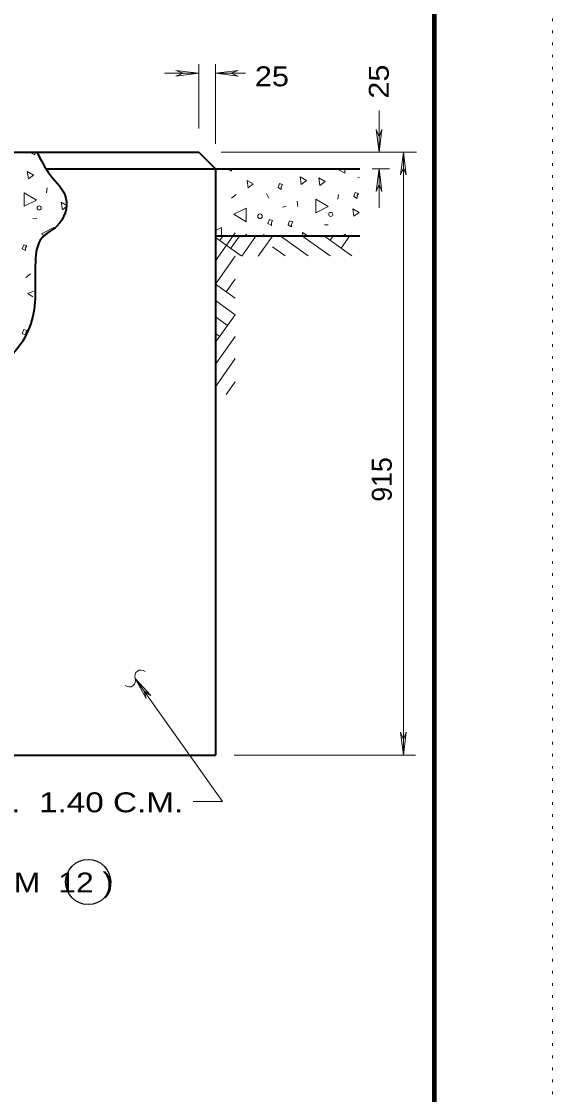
# Model space of a CAD drawing. Extents: x 312583 to 312854, y 144419 to 144597.
# Drawn here: x 312833.23 to 312853.5, y 144508.27 to 144549.21 of the extents above; entities that cross this region are included whole.
import ezdxf

# ---------------------------------------------------------------- set-up
doc = ezdxf.new("R2010")
doc.units = 0
doc.header["$LTSCALE"] = 0.3
doc.linetypes.add('DOTTED', pattern=[1.5, 0.3, -1.2])
for name, color, linetype, lineweight in [('1', 7, 'Continuous', 25), ('2', 7, 'Continuous', 13), ('63', 7, 'DOTTED', 13)]:
    doc.layers.add(name, color=color, linetype=linetype, lineweight=lineweight)

msp = doc.modelspace()

# ---------------------------------------------------------------- linework, layer by layer
at = {"layer": '1', "lineweight": 158}
msp.add_line((312849, 144423.1446), (312849, 144585.0846), dxfattribs=at)
at = {"layer": '1', "lineweight": 40}
for p, q in [((312778.6606, 144544.2243), (312839.994, 144544.2243)), ((312839.994, 144544.2243), (312840.6303, 144543.5879)), ((312834.1903, 144543.5879), (312846.1426, 144543.5879)), ((312840.6303, 144543.5879), (312840.6303, 144521.2243)), ((312840.6303, 144541.0349), (312846.1426, 144541.0349)), ((312778.0166, 144521.2243), (312840.6303, 144521.2243))]:
    msp.add_line(p, q, dxfattribs=at)
msp.add_spline([(312833.8223, 144544.2243), (312834.3283, 144543.3579), (312834.9263, 144542.4763), (312834.5813, 144541.4029), (312834.014, 144540.9583), (312833.761, 144540.0383), (312833.6306, 144537.8303), (312833.094, 144536.7569), (312832.9406, 144536.5653), (312832.0206, 144535.7756), (312831.461, 144536.0056), (312830.6023, 144535.9059), (312829.8356, 144535.9749), (312828.9693, 144535.7526), (312827.919, 144535.7143), (312827.2903, 144535.9213), (312826.562, 144535.6223), (312826.4623, 144535.5226), (312825.757, 144535.6376), (312824.6606, 144534.9553), (312824.377, 144534.8939), (312823.319, 144535.4536), (312821.7166, 144535.5303), (312821.3793, 144535.0703)], degree=3, dxfattribs=at)
at = {"layer": '2'}
for p, q in [((312839.994, 144545.1289), (312839.994, 144547.5823)), ((312840.6303, 144544.5386), (312840.6303, 144547.5823)), ((312838.6906, 144547.2373), (312839.994, 144547.2373)), ((312839.1276, 144547.3446), (312839.4036, 144547.2373)), ((312839.994, 144547.2373), (312839.1276, 144547.3446)), ((312839.1276, 144547.1299), (312839.4036, 144547.2373)), ((312839.994, 144547.2373), (312839.1276, 144547.1299)), ((312840.6303, 144547.2373), (312841.4966, 144547.3446)), ((312840.6303, 144547.2373), (312841.7803, 144547.2373)), ((312840.6303, 144547.2373), (312841.4966, 144547.1299)), ((312841.4966, 144547.3446), (312841.2206, 144547.2373)), ((312841.4966, 144547.1299), (312841.2206, 144547.2373)), ((312846.8789, 144544.2243), (312846.8789, 144545.8189)), ((312846.7716, 144545.0906), (312846.8789, 144544.8146)), ((312846.8789, 144544.2243), (312846.7716, 144545.0906)), ((312846.9863, 144545.0906), (312846.8789, 144544.8146)), ((312846.8789, 144544.2243), (312846.9863, 144545.0906)), ((312840.8526, 144544.2243), (312848.3046, 144544.2243)), ((312847.8096, 144544.2243), (312847.7023, 144543.3579)), ((312847.8096, 144521.2243), (312847.8096, 144544.2243)), ((312847.8096, 144544.2243), (312847.9169, 144543.3579)), ((312840.6303, 144543.3426), (312840.661, 144543.3349)), ((312845.284, 144543.5879), (312845.5676, 144543.4193)), ((312845.5676, 144543.4193), (312845.5676, 144543.5879)), ((312846.6103, 144543.5879), (312847.2771, 144543.5879)), ((312846.8789, 144543.5879), (312846.7716, 144542.7216)), ((312846.8789, 144542.1006), (312846.8789, 144543.5879)), ((312846.8789, 144543.5879), (312846.9863, 144542.7216)), ((312847.7023, 144543.3579), (312847.8096, 144543.6339)), ((312847.9169, 144543.3579), (312847.8096, 144543.6339)), ((312846.0736, 144543.2583), (312846.135, 144543.2659)), ((312846.7716, 144542.7216), (312846.8789, 144542.9976)), ((312846.9863, 144542.7216), (312846.8789, 144542.9976)), ((312834.1826, 144542.6756), (312834.2056, 144542.8673)), ((312841.4276, 144542.6066), (312841.2513, 144542.4686)), ((312842.5776, 144542.6449), (312842.6696, 144542.4763)), ((312845.307, 144542.4303), (312845.33, 144542.6143)), ((312834.796, 144542.0316), (312834.9646, 144542.1619)), ((312843.191, 144542.1236), (312843.3366, 144542.1619)), ((312843.7506, 144542.3536), (312843.7736, 144542.1466)), ((312833.669, 144541.6943), (312833.8146, 144541.7019)), ((312844.7933, 144541.4489), (312844.939, 144541.4566)), ((312841.3893, 144541.1423), (312840.6303, 144540.0766)), ((312841.6193, 144540.2683), (312840.6303, 144540.9736)), ((312840.9216, 144541.0196), (312840.8066, 144540.8509)), ((312841.5503, 144541.0196), (312841.2206, 144540.5596)), ((312842.179, 144541.0196), (312841.6346, 144540.2606)), ((312841.7113, 144541.0349), (312841.8263, 144541.0963)), ((312842.8076, 144541.0196), (312842.2633, 144540.2606)), ((312844.1723, 144540.2683), (312843.1066, 144541.0349)), ((312845.0156, 144540.2683), (312843.973, 144541.0119)), ((312845.8436, 144540.2683), (312844.7626, 144541.0426)), ((312845.1306, 144541.0349), (312845.0156, 144540.8663)), ((312845.7593, 144541.0349), (312845.4296, 144540.5673)), ((312843.2906, 144540.2683), (312842.8076, 144540.6133)), ((312841.3893, 144540.2606), (312840.6303, 144539.1949)), ((312833.5693, 144539.5783), (312833.393, 144539.4479)), ((312841.3893, 144539.3789), (312841.0443, 144538.8959)), ((312840.6303, 144539.1949), (312841.3893, 144538.6506)), ((312840.6303, 144538.5663), (312841.3893, 144538.0219)), ((312841.3893, 144538.0219), (312840.615, 144536.9409)), ((312840.6303, 144537.9376), (312841.098, 144537.6079)), ((312840.6303, 144537.3089), (312840.799, 144537.1939)), ((312841.3893, 144537.1939), (312840.6533, 144536.1513)), ((312841.3893, 144536.3506), (312840.6303, 144535.2773)), ((312841.3893, 144535.4689), (312841.0443, 144534.9859)), ((312837.5713, 144524.1453), (312837.9853, 144523.3786)), ((312837.5713, 144524.1453), (312838.1616, 144523.5013)), ((312837.9853, 144523.3786), (312837.9086, 144523.6623)), ((312838.1616, 144523.5013), (312837.9086, 144523.6623)), ((312847.7023, 144522.0906), (312847.8096, 144521.8146)), ((312847.8096, 144521.2243), (312847.7023, 144522.0906)), ((312847.9169, 144522.0906), (312847.8096, 144521.8146)), ((312847.8096, 144521.2243), (312847.9169, 144522.0906)), ((312841.3433, 144521.2243), (312848.2673, 144521.2243))]:
    msp.add_line(p, q, dxfattribs=at)
for points in [[(312833.6153, 144544.2243), (312833.6076, 144544.1936), (312833.738, 144544.1246), (312833.738, 144544.2243)], [(312833.9833, 144543.9483), (312833.968, 144543.9483), (312833.991, 144543.9329)], [(312841.121, 144543.5879), (312841.1133, 144543.5649), (312841.2436, 144543.4959), (312841.2436, 144543.5879)], [(312834.9646, 144542.1926), (312834.75, 144542.3153), (312834.796, 144542.0316)], [(312834.4663, 144541.2573), (312834.4663, 144541.3493), (312833.9986, 144541.1116), (312834.129, 144541.0349)], [(312840.8603, 144541.0349), (312840.8603, 144541.3493), (312840.6303, 144541.2343)], [(312842.5546, 144541.0349), (312842.4703, 144541.0886), (312842.478, 144541.0349)], [(312844.1646, 144541.0349), (312843.95, 144541.1653), (312843.9653, 144541.0349)], [(312845.5983, 144541.0349), (312845.5983, 144541.0963), (312845.468, 144541.0349)], [(312833.6843, 144538.9266), (312833.4773, 144538.8269), (312833.669, 144538.7119)], [(312839.787, 144519.4456), (312840.9063, 144519.4456), (312837.5713, 144524.1453)]]:
    msp.add_lwpolyline(points, dxfattribs=at)
for points in [[(312833.4926, 144543.2046), (312833.6843, 144543.3503), (312833.4466, 144543.4883)], [(312841.88, 144542.8673), (312842.0716, 144543.0129), (312841.8416, 144543.1509)], [(312843.145, 144542.9056), (312843.1986, 144542.9899), (312843.076, 144543.0283), (312843.0223, 144542.8749), (312843.145, 144542.8059)], [(312843.9116, 144542.9976), (312844.1033, 144543.1433), (312843.8733, 144543.2813)], [(312844.617, 144542.9593), (312844.8163, 144543.1049), (312844.5786, 144543.2429)], [(312833.3316, 144542.6756), (312833.3316, 144542.1619), (312833.7993, 144542.3996)], [(312846.043, 144542.5683), (312846.089, 144542.6449), (312845.9663, 144542.6833), (312845.9126, 144542.5299), (312846.043, 144542.4609)], [(312844.4636, 144542.4303), (312844.4636, 144541.9166), (312844.9313, 144542.1466)], [(312841.8033, 144541.5716), (312841.8033, 144542.0853), (312841.3356, 144541.8553)], [(312845.9203, 144541.7786), (312846.1196, 144541.9243), (312845.882, 144542.0699)], [(312842.7693, 144541.5333), (312842.8153, 144541.6176), (312842.7003, 144541.6559), (312842.639, 144541.5026), (312842.7693, 144541.4336)], [(312843.536, 144541.4796), (312843.582, 144541.5639), (312843.4593, 144541.6023), (312843.4056, 144541.4489), (312843.536, 144541.3799)], [(312833.3853, 144540.5749), (312833.4313, 144540.6516), (312833.3163, 144540.6899), (312833.255, 144540.5366), (312833.3853, 144540.4676)], [(312833.393, 144537.3396), (312833.439, 144537.4239), (312833.324, 144537.4623), (312833.2626, 144537.3089), (312833.393, 144537.2399)]]:
    msp.add_lwpolyline(points, close=True, dxfattribs=at)
for centre, radius in [((312833.9051, 144542.0987), 0.0784), ((312842.3354, 144541.7802), 0.0865), ((312845.0351, 144541.8507), 0.0784)]:
    msp.add_circle(centre, radius, dxfattribs=at)
at = {"layer": '2', "lineweight": 25}
msp.add_circle((312835.7767, 144516.3809), 0.8608, dxfattribs=at)
at = {"layer": '2'}
for centre, start, end in [((312837.3449, 144524.0613), 230.36848, 20.36848), ((312837.7939, 144524.228), 50.36848, 200.36848)]:
    msp.add_arc(centre, 0.2395, start, end, dxfattribs=at)
at = {"layer": '63'}
msp.add_lwpolyline([(312601.2, 144418.5846), (312853.5, 144418.5846), (312853.5, 144596.7846)], dxfattribs=at)

# ---------------------------------------------------------------- texts
at = {"layer": '2'}
for s, width, p in [('25 ', 1.15, (312842.1378, 144546.739)), ('APPROX.  1.40 C.M.', 1.25, (312827.5441, 144519.0401)), ('(SEE ITEM  12 )', 1.2, (312827.8555, 144515.9802))]:
    msp.add_text(s, height=0.76, dxfattribs=dict(at, width=width)).set_placement(p)
at = {"layer": '2', "width": 1.15}
msp.add_text('25 ', height=0.76, rotation=90, dxfattribs=at).set_placement((312847.249, 144546.2674))
at = {"layer": '2'}
msp.add_text('915', height=0.76, rotation=90, dxfattribs=at).set_placement((312847.3624, 144530.8902))

doc.saveas('drawing.dxf')
